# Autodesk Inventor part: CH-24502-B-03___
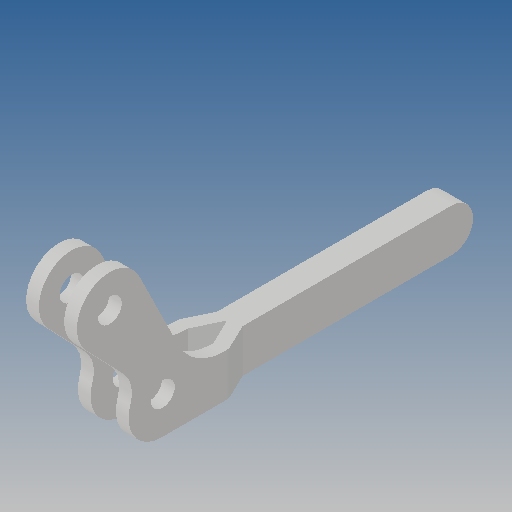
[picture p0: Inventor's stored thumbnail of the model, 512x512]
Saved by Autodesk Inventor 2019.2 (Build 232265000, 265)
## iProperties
Created: 2010-06
Part Number: CH-24502-B-03___
Material: Ogólny
Document SubType Name: Modeling
Designer: CADENGINEERING4
Density: 1 g/cm^3
Appearance: Domyślna
Author: CADENGINEERING4
Revision Number: ANY
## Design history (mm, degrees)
feature "NONE"
node "Bryła1"
